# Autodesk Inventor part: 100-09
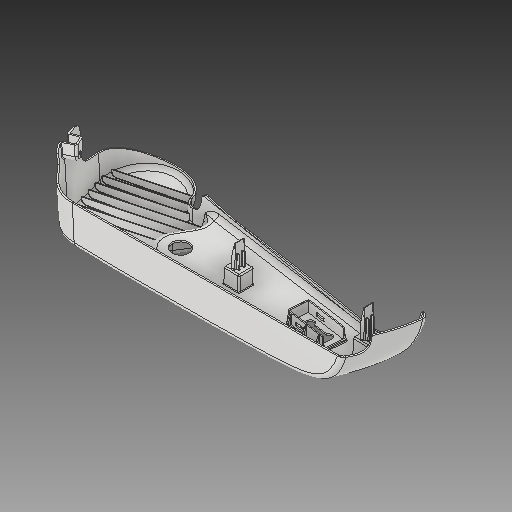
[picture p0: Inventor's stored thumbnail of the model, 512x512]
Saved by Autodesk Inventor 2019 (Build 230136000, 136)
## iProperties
Company: Autodesk Inc.
Created: 2007-12
Part Number: 100-09
Material: ABS Plastic
Description: SIDE PLASTIC COVER
Document SubType Name: Modeling
Designer: Autodesk Inc.
Density: 1.06 g/cm^3
Appearance: Smooth - White
Component Category: Side Component
Author: Inventor
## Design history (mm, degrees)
derived "Side Cover.ipt"
  sketch "Sketch1"
    geometry: L1 (-31.666, 125)-(201.012, 125) reference; 1 further point
  sketch "Sketch2"
    geometry: L1 (-236.74, 122.454)-(-244.581, 340.953) reference; L2 (-244.581, 340.953)-(-128.628, 329.837) reference; L3 (-128.628, 329.837)-(-155.756, 97.766) reference
  sketch "Sketch3"
    geometry: L1 (0, 70)-(50, 70) reference; L2 (65, 55)-(65, 0) reference; A1 r 15 centre (50, 55) between (65, 55) and (50, 70) reference; 1 further point
  sketch "Sketch4"
    geometry: A1 r 350 centre (-41.225, 356.621) between (-30.735, 6.778) and (33.955, 14.791) reference; 3 further points
  sketch "Sketch5"
    geometry: C1 r 5.025 at (-116.996, 110) reference; C2 r 15 at (-116.996, 110) reference
  sketch "Sketch6"
    geometry: L1 (-16.863, -65.429)-(-261.287, -65.429) reference; L2 (0, 0)-(-319.709, 0) reference; 1 further point; 1 other entity
    constraints: 1 other
  sketch "Sketch12"
    geometry: L1 (-24.5, 21)-(-5.5, 21) reference; L2 (-5.5, 27)-(-24.5, 27) reference; L3 (-24.5, 21)-(-5.5, 27) reference; L4 (361.35, 41.429)-(-256.934, 41.429) reference; L5 (-25, 24)-(-25, 41.429) reference; L6 (-5, 24)-(-5, 41.429) reference; C1 r 2.75 at (-15, 24) reference; A1 r 10 centre (-15, 24) between (-25, 24) and (-5, 24) reference; 1 further point
  sketch "Sketch14"
    geometry: L1 (-5, 24)-(-5, 41.429) reference; L2 (-25, 41.429)-(-25, 24) reference; L3 (-89.525, -67.484)-(-90.11, -65.841) reference; L4 (-5, 41.429)-(-25, 41.429) reference; L5 (-7.5, 24)-(-7.5, 38.929) reference; L6 (-7.5, 38.929)-(-22.5, 38.929) reference; L7 (-22.5, 38.929)-(-22.5, 24) reference; L8 (-22.5, 38.929)-(-22.5, 53.929) reference; L9 (-22.5, 53.929)-(-7.5, 53.929) reference; L10 (-7.5, 53.929)-(-7.5, 38.929) reference; A1 r 10 centre (-15, 24) between (-25, 24) and (-5, 24) reference; A2 r 7.5 centre (-15, 24) between (-22.5, 24) and (-7.5, 24) reference; 12 further points
  sketch "Sketch16"
    geometry: L1 (25, 24)-(25, 41.429) reference; L2 (5, 41.429)-(5, 24) reference; L3 (25, 41.429)-(5, 41.429) reference; C1 r 2.75 at (15, 24) reference; A1 r 10 centre (15, 24) between (5, 24) and (25, 24) reference
  sketch "Sketch17"
    geometry: L1 (-229.175, 211.817)-(-293.224, 194.655) reference; L2 (-229.175, 211.817)-(-215.205, 159.682) reference; L3 (0, 27.871)-(0, 242.475) reference; L4 (-224.775, 195.396)-(-288.824, 178.234) reference; L5 (-220.375, 178.976)-(-284.424, 161.814) reference; L6 (-215.975, 162.555)-(-280.025, 145.393) reference; L7 (-211.575, 146.134)-(-275.625, 128.972) reference; L8 (-207.175, 129.713)-(-271.225, 112.551) reference; L9 (-202.775, 113.293)-(-266.825, 96.131) reference; L10 (-198.375, 96.872)-(-262.425, 79.71) reference
    constraints: 1 other
  sketch "Sketch18"
    geometry: L1 (-539.384, 57.752)-(304.194, 148.909) reference; L2 (-68.703, 108.614)-(-81.627, 107.217) reference; L3 (-72.33, 114.257)-(-71.041, 102.326) reference; L4 (-79.289, 113.505)-(-78, 101.574) reference; 1 further point; 1 other entity
    constraints: 1 other
  sketch "Sketch19"
    geometry: L1 (-2.537, -0.923)-(-7.753, 13.408) reference; L2 (-7.753, 13.408)-(9.509, 18.232) reference; L3 (9.509, 18.232)-(2.537, -0.923) reference; L4 (0, 0)-(0, 20.344) reference; C1 r 2.5 at (0, 0) reference; A1 r 2.7 centre (0, 0) between (-2.537, -0.923) and (2.537, -0.923) reference; 1 further point
  sketch "Sketch20"
    geometry: L1 (-539.384, 57.752)-(304.194, 148.909) reference; L2 (-280.47, 85.73)-(-267.545, 87.127) reference; L3 (-269.883, 80.839)-(-271.172, 92.77) reference; L4 (-276.842, 80.087)-(-278.132, 92.018) reference; 1 further point; 1 other entity
    constraints: 1 other
  sketch "Sketch21"
    geometry: L1 (0, 0)-(0, 13.676) reference; L2 (-2.537, -0.923)-(-8.333, 15) reference; L3 (-8.333, 15)-(8.333, 15) reference; L4 (8.333, 15)-(2.537, -0.923) reference; C1 r 2.5 at (0, 0) reference; A1 r 2.7 centre (0, 0) between (-2.537, -0.923) and (2.537, -0.923) reference
  workplane "Work Plane1"
  workplane "Work Plane2"
  workplane "Work Plane3"
  workplane "Work Plane4"
  workplane "Work Plane7"
  workplane "Work Plane8"
  workplane "Work Plane9"
  workaxis "Work Axis1"
  workpoint "Work Point1"
  workpoint "Work Point2"
  workpoint "Work Point3"
  workpoint "Work Point4"
  workpoint "Work Point5"
  workpoint "Work Point6"
feature "Solid1::Side Cover.ipt"
tag "TaggingFeature1"
workplane "Work Plane6"
body "Srf1"
body "Srf2"
body "Srf3"
body "Srf4"
body "Srf5"
body "Srf6"
body "Srf7"
body "Srf8"
body "Srf9"
body "Srf10"
body "Srf11"
body "Srf12"
body "Srf13"
body "Srf14"
body "Srf15"
body "Srf16"
body "Srf17"
body "Srf18"
body "Solid1"
feature "Srf1::Derived"
feature "Srf2::Derived"
feature "Srf3::Derived"
feature "Srf4::Derived"
feature "Srf5::Derived"
feature "Srf6::Derived"
feature "Srf7::Derived"
feature "Srf8::Derived"
feature "Srf9::Derived"
feature "Srf10::Derived"
feature "Srf11::Derived"
feature "Srf12::Derived"
feature "Srf13::Derived"
feature "Srf14::Derived"
feature "Srf15::Derived"
feature "Srf16::Derived"
feature "Srf17::Derived"
feature "Srf18::Derived"
